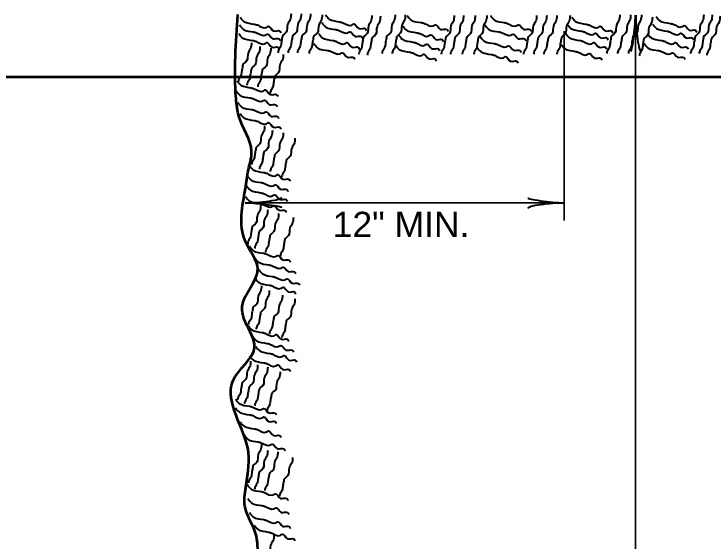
# Model space of a CAD drawing. Extents: x -488 to 193, y 19 to 459.
# Drawn here: x -190.5 to -135, y 277.1 to 318.9 of the extents above; entities that cross this region are included whole.
import ezdxf
from ezdxf.enums import TextEntityAlignment as Align

# ---------------------------------------------------------------- set-up
doc = ezdxf.new("R2010")
doc.units = 0
doc.header["$LTSCALE"] = 0.8
doc.layers.add('1', color=7, linetype='Continuous', lineweight=40)

msp = doc.modelspace()

# ---------------------------------------------------------------- linework, layer by layer
at = {"layer": '1', "lineweight": 35}
for p, q in [((-141.2341, 224.8116), (-141.2341, 318.7816)), ((-146.8977, 317.5241), (-146.8977, 302.5241)), ((-146.8977, 303.9148), (-172.1522, 303.9148))]:
    msp.add_line(p, q, dxfattribs=at)
at = {"layer": '1', "lineweight": 53}
msp.add_line((-271.5283, 313.9212), (-111.5283, 313.9212), dxfattribs=at)
at = {"layer": '1'}
for centre, major_axis, ratio, start_param, end_param in [((-141.4457, 317.6611), (-0.1757, -1.7565), 0.07063, 6.2823074, 8.5597026), ((-141.4457, 317.6611), (-0.1757, -1.7565), 0.07063, 6.2823074, 8.5597026), ((-140.9578, 317.6904), (-0.1562, 1.7857), 0.122415, 0.8963533, 3.1415927), ((-140.9578, 317.6904), (-0.1562, 1.7857), 0.122415, 0.8963533, 3.1415927), ((-171.0317, 303.7032), (1.7565, -0.1757), 0.07063, 6.2823074, 8.5597026), ((-171.0317, 303.7032), (1.7565, -0.1757), 0.07063, 6.2823074, 8.5597026), ((-171.0611, 304.1911), (-1.7857, -0.1562), 0.122415, 0.8963533, 3.1415927), ((-171.0611, 304.1911), (-1.7857, -0.1562), 0.122415, 0.8963533, 3.1415927), ((-147.9889, 303.6385), (1.7857, 0.1562), 0.122415, 0.8963533, 3.1415927), ((-148.0182, 304.1264), (1.7565, -0.1757), 0.07063, 3.1407148, 5.41811)]:
    msp.add_ellipse(centre, major_axis=major_axis, ratio=ratio, start_param=start_param, end_param=end_param, dxfattribs=at)
for points in [[(-168.5302, 318.8906), (-168.6157, 318.4057), (-168.801, 318.0633), (-168.9079, 317.457), (-169.2147, 317.1361), (-169.2359, 317.0149), (-169.3001, 316.6511), (-169.3642, 316.2873), (-169.5497, 315.9451), (-169.5711, 315.8237)], [(-167.7299, 318.8906), (-167.8154, 318.4057), (-168.0007, 318.0633), (-168.1077, 317.457), (-168.4144, 317.1361), (-168.4357, 317.0149), (-168.4998, 316.6511), (-168.5639, 316.2873), (-168.7494, 315.9451), (-168.7708, 315.8237)], [(-166.9913, 318.8906), (-167.0768, 318.4057), (-167.2621, 318.0633), (-167.369, 317.457), (-167.6757, 317.1361), (-167.697, 317.0149), (-167.7612, 316.6511), (-167.8252, 316.2873), (-168.0108, 315.9451), (-168.0322, 315.8237)], [(-172.5642, 318.6382), (-172.2713, 318.3047), (-171.4388, 318.0817), (-171.201, 318.018), (-170.4875, 317.8268), (-170.3367, 317.9138), (-169.9246, 317.5486), (-169.4172, 317.5399), (-169.3301, 317.3893)], [(-166.0678, 318.829), (-166.1533, 318.3441), (-166.3387, 318.0018), (-166.4456, 317.3954), (-166.7523, 317.0745), (-166.7736, 316.9533), (-166.8377, 316.5895), (-166.9018, 316.2258), (-167.0873, 315.8835), (-167.1087, 315.7622)], [(-165.7928, 318.8229), (-165.4999, 318.4893), (-164.6674, 318.2663), (-164.4296, 318.2027), (-163.7161, 318.0114), (-163.5652, 318.0985), (-163.1532, 317.7332), (-162.6457, 317.7246), (-162.5587, 317.5739)], [(-162.1281, 318.7674), (-162.2136, 318.2825), (-162.3989, 317.9402), (-162.5058, 317.3338), (-162.8126, 317.0129), (-162.8338, 316.8918), (-162.898, 316.5279), (-162.9621, 316.1642), (-163.1476, 315.8219), (-163.169, 315.7006)], [(-161.4509, 318.7059), (-161.5364, 318.221), (-161.7217, 317.8787), (-161.8287, 317.2723), (-162.1354, 316.9514), (-162.1567, 316.8302), (-162.2208, 316.4664), (-162.2849, 316.1027), (-162.4704, 315.7604), (-162.4918, 315.6391)], [(-160.2813, 318.829), (-160.3668, 318.3441), (-160.5522, 318.0018), (-160.6591, 317.3954), (-160.9658, 317.0745), (-160.9871, 316.9533), (-161.0512, 316.5895), (-161.1153, 316.2258), (-161.3008, 315.8835), (-161.3222, 315.7622)], [(-159.481, 318.829), (-159.5665, 318.3441), (-159.7518, 318.0018), (-159.8587, 317.3954), (-160.1655, 317.0745), (-160.1867, 316.9533), (-160.2509, 316.5895), (-160.315, 316.2258), (-160.5005, 315.8835), (-160.5219, 315.7622)], [(-159.3291, 318.7614), (-159.0362, 318.4278), (-158.2037, 318.2048), (-157.9658, 318.1412), (-157.2523, 317.9499), (-157.1015, 318.037), (-156.6894, 317.6717), (-156.182, 317.6631), (-156.0949, 317.5124)], [(-155.6028, 318.7674), (-155.6883, 318.2825), (-155.8737, 317.9402), (-155.9806, 317.3338), (-156.2873, 317.0129), (-156.3086, 316.8918), (-156.3727, 316.5279), (-156.4368, 316.1642), (-156.6223, 315.8219), (-156.6437, 315.7006)], [(-154.8642, 318.7674), (-154.9497, 318.2825), (-155.135, 317.9402), (-155.2419, 317.3338), (-155.5487, 317.0129), (-155.5699, 316.8918), (-155.6341, 316.5279), (-155.6982, 316.1642), (-155.8837, 315.8219), (-155.9051, 315.7006)], [(-153.9408, 318.7674), (-154.0263, 318.2825), (-154.2116, 317.9402), (-154.3185, 317.3338), (-154.6252, 317.0129), (-154.6465, 316.8918), (-154.7107, 316.5279), (-154.7747, 316.1642), (-154.9603, 315.8219), (-154.9817, 315.7006)], [(-153.0174, 318.7674), (-153.1029, 318.2825), (-153.2883, 317.9402), (-153.3952, 317.3338), (-153.7019, 317.0129), (-153.7232, 316.8918), (-153.7873, 316.5279), (-153.8514, 316.1642), (-154.0369, 315.8219), (-154.0583, 315.7006)], [(-152.7423, 318.7614), (-152.4494, 318.4278), (-151.6169, 318.2048), (-151.3791, 318.1412), (-150.6656, 317.9499), (-150.5147, 318.037), (-150.1027, 317.6717), (-149.5952, 317.6631), (-149.5082, 317.5124)], [(-149.0777, 318.7675), (-149.1632, 318.2826), (-149.3485, 317.9402), (-149.4554, 317.3339), (-149.7622, 317.013), (-149.7834, 316.8918), (-149.8476, 316.528), (-149.9117, 316.1642), (-150.0972, 315.822), (-150.1186, 315.7007)], [(-148.2774, 318.7675), (-148.3629, 318.2826), (-148.5482, 317.9402), (-148.6552, 317.3339), (-148.9619, 317.013), (-148.9832, 316.8918), (-149.0473, 316.528), (-149.1114, 316.1642), (-149.2969, 315.822), (-149.3183, 315.7007)], [(-147.4772, 318.7675), (-147.5627, 318.2826), (-147.748, 317.9402), (-147.8549, 317.3339), (-148.1617, 317.013), (-148.1829, 316.8918), (-148.2471, 316.528), (-148.3112, 316.1642), (-148.4967, 315.822), (-148.5181, 315.7007)], [(-146.4307, 318.7675), (-146.5162, 318.2826), (-146.7015, 317.9402), (-146.8084, 317.3339), (-147.1152, 317.013), (-147.1364, 316.8918), (-147.2006, 316.528), (-147.2647, 316.1642), (-147.4502, 315.822), (-147.4716, 315.7007)], [(-146.2788, 318.6383), (-145.9858, 318.3048), (-145.1533, 318.0817), (-144.9155, 318.0181), (-144.202, 317.8268), (-144.0512, 317.9139), (-143.6391, 317.5487), (-143.1317, 317.54), (-143.0446, 317.3893)], [(-142.4909, 318.829), (-142.5764, 318.3441), (-142.7618, 318.0018), (-142.8687, 317.3954), (-143.1754, 317.0745), (-143.1967, 316.9533), (-143.2608, 316.5895), (-143.3249, 316.2258), (-143.5104, 315.8835), (-143.5318, 315.7622)], [(-141.6291, 318.829), (-141.7146, 318.3441), (-141.8999, 318.0018), (-142.0068, 317.3954), (-142.3136, 317.0745), (-142.3348, 316.9533), (-142.399, 316.5895), (-142.4631, 316.2258), (-142.6486, 315.8835), (-142.67, 315.7622)], [(-140.7672, 318.829), (-140.8527, 318.3441), (-141.0381, 318.0018), (-141.145, 317.3954), (-141.4518, 317.0745), (-141.473, 316.9533), (-141.5372, 316.5895), (-141.6012, 316.2258), (-141.7867, 315.8835), (-141.8082, 315.7622)], [(-139.9054, 318.6443), (-139.9909, 318.1594), (-140.1762, 317.8171), (-140.2832, 317.2107), (-140.5899, 316.8898), (-140.6112, 316.7687), (-140.6753, 316.4048), (-140.7394, 316.0411), (-140.9249, 315.6988), (-140.9463, 315.5775)], [(-139.6304, 318.6997), (-139.3375, 318.3662), (-138.505, 318.1432), (-138.2672, 318.0795), (-137.5537, 317.8882), (-137.4028, 317.9753), (-136.9907, 317.6101), (-136.4833, 317.6014), (-136.3963, 317.4507)], [(-135.8426, 318.829), (-135.9281, 318.3441), (-136.1134, 318.0018), (-136.2203, 317.3954), (-136.5271, 317.0745), (-136.5483, 316.9533), (-136.6125, 316.5895), (-136.6766, 316.2258), (-136.8621, 315.8835), (-136.8835, 315.7622)], [(-135.1654, 318.829), (-135.2509, 318.3441), (-135.4363, 318.0018), (-135.5432, 317.3954), (-135.8499, 317.0745), (-135.8712, 316.9533), (-135.9353, 316.5895), (-135.9994, 316.2258), (-136.1849, 315.8835), (-136.2063, 315.7622)], [(-134.5498, 318.7058), (-134.6353, 318.2209), (-134.8207, 317.8786), (-134.9276, 317.2722), (-135.2343, 316.9513), (-135.2556, 316.8302), (-135.3197, 316.4663), (-135.3838, 316.1026), (-135.5693, 315.7603), (-135.5907, 315.639)], [(-172.6258, 318.0227), (-172.3329, 317.6891), (-171.5004, 317.4661), (-171.2626, 317.4024), (-170.5491, 317.2112), (-170.3982, 317.2982), (-169.9862, 316.933), (-169.4787, 316.9243), (-169.3917, 316.7737)], [(-166.1007, 318.2073), (-165.8077, 317.8737), (-164.9752, 317.6508), (-164.7374, 317.5871), (-164.0239, 317.3958), (-163.8731, 317.4829), (-163.461, 317.1177), (-162.9536, 317.109), (-162.8665, 316.9583)], [(-159.6985, 317.9612), (-159.4056, 317.6276), (-158.5731, 317.4046), (-158.3353, 317.3409), (-157.6217, 317.1497), (-157.4709, 317.2367), (-157.0588, 316.8715), (-156.5514, 316.8628), (-156.4643, 316.7122)], [(-153.1732, 318.0227), (-152.8803, 317.6891), (-152.0478, 317.4661), (-151.81, 317.4024), (-151.0965, 317.2112), (-150.9457, 317.2982), (-150.5336, 316.933), (-150.0262, 316.9243), (-149.9391, 316.7737)], [(-146.6481, 318.0842), (-146.3552, 317.7507), (-145.5227, 317.5277), (-145.2848, 317.464), (-144.5713, 317.2727), (-144.4205, 317.3598), (-144.0084, 316.9946), (-143.501, 316.9859), (-143.4139, 316.8352)], [(-139.8766, 318.0842), (-139.5837, 317.7506), (-138.7512, 317.5276), (-138.5133, 317.4639), (-137.7998, 317.2727), (-137.649, 317.3597), (-137.2369, 316.9945), (-136.7295, 316.9858), (-136.6424, 316.8352)], [(-172.6873, 317.3455), (-172.3944, 317.0119), (-171.5619, 316.7889), (-171.3241, 316.7253), (-170.6106, 316.534), (-170.4597, 316.6211), (-170.0477, 316.2558), (-169.5402, 316.2472), (-169.4532, 316.0965)], [(-166.3468, 317.3455), (-166.0539, 317.0119), (-165.2214, 316.7889), (-164.9836, 316.7253), (-164.2701, 316.534), (-164.1192, 316.6211), (-163.7072, 316.2558), (-163.1997, 316.2472), (-163.1127, 316.0965)], [(-160.0062, 317.2224), (-159.7133, 316.8888), (-158.8808, 316.6658), (-158.643, 316.6022), (-157.9295, 316.4109), (-157.7787, 316.498), (-157.3666, 316.1327), (-156.8592, 316.1241), (-156.7721, 315.9734)], [(-146.7712, 317.3456), (-146.4783, 317.012), (-145.6457, 316.789), (-145.4079, 316.7253), (-144.6944, 316.5341), (-144.5436, 316.6212), (-144.1315, 316.2559), (-143.6241, 316.2473), (-143.537, 316.0966)], [(-140.3075, 317.3455), (-140.0146, 317.0119), (-139.1821, 316.7889), (-138.9442, 316.7253), (-138.2308, 316.534), (-138.0799, 316.6211), (-137.6678, 316.2558), (-137.1604, 316.2472), (-137.0733, 316.0965)], [(-153.5426, 317.0993), (-153.2497, 316.7657), (-152.4172, 316.5428), (-152.1793, 316.4791), (-151.4658, 316.2878), (-151.315, 316.3749), (-150.9029, 316.0097), (-150.3955, 316.001), (-150.3084, 315.8503)], [(-171.6697, 316.6129), (-171.7552, 316.128), (-171.9405, 315.7857), (-172.0474, 315.1793), (-172.3542, 314.8584), (-172.3754, 314.7373), (-172.4396, 314.3734), (-172.5037, 314.0097), (-172.6892, 313.6674), (-172.7106, 313.5461)], [(-170.9926, 316.3051), (-171.0781, 315.8202), (-171.2634, 315.4778), (-171.3703, 314.8715), (-171.6771, 314.5506), (-171.6983, 314.4294), (-171.7625, 314.0656), (-171.8266, 313.7018), (-172.0121, 313.3596), (-172.0335, 313.2382)], [(-170.1308, 316.182), (-170.2163, 315.6971), (-170.4016, 315.3547), (-170.5085, 314.7484), (-170.8152, 314.4275), (-170.8365, 314.3063), (-170.9007, 313.9425), (-170.9647, 313.5788), (-171.1502, 313.2365), (-171.1717, 313.1152)], [(-166.7163, 316.5453), (-166.4233, 316.2117), (-165.5908, 315.9887), (-165.353, 315.925), (-164.6395, 315.7337), (-164.4887, 315.8208), (-164.0766, 315.4556), (-163.5692, 315.4469), (-163.4821, 315.2962)], [(-160.2525, 316.4222), (-159.9596, 316.0886), (-159.1271, 315.8656), (-158.8893, 315.8019), (-158.1757, 315.6107), (-158.0249, 315.6977), (-157.6128, 315.3325), (-157.1054, 315.3238), (-157.0183, 315.1732)], [(-153.7888, 316.2375), (-153.4959, 315.9039), (-152.6634, 315.6809), (-152.4256, 315.6173), (-151.7121, 315.426), (-151.5613, 315.5131), (-151.1492, 315.1478), (-150.6418, 315.1392), (-150.5547, 314.9885)], [(-147.1406, 316.4837), (-146.8477, 316.1502), (-146.0152, 315.9272), (-145.7773, 315.8635), (-145.0638, 315.6722), (-144.913, 315.7593), (-144.5009, 315.3941), (-143.9935, 315.3854), (-143.9064, 315.2347)], [(-140.5538, 316.5453), (-140.2608, 316.2117), (-139.4283, 315.9887), (-139.1905, 315.925), (-138.477, 315.7337), (-138.3262, 315.8208), (-137.9141, 315.4556), (-137.4067, 315.4469), (-137.3196, 315.2962)], [(-169.1458, 315.6895), (-169.2313, 315.2046), (-169.4167, 314.8623), (-169.5236, 314.2559), (-169.8303, 313.935), (-169.8516, 313.8138), (-169.9158, 313.45), (-169.9798, 313.0863), (-170.1653, 312.744), (-170.1867, 312.6227)], [(-172.8105, 313.5905), (-172.5176, 313.2569), (-171.6851, 313.0339), (-171.4472, 312.9702), (-170.7337, 312.779), (-170.5829, 312.8661), (-170.1708, 312.5008), (-169.6634, 312.4922), (-169.5763, 312.3415)], [(-172.872, 312.7903), (-172.5791, 312.4567), (-171.7466, 312.2337), (-171.5087, 312.17), (-170.7952, 311.9787), (-170.6444, 312.0658), (-170.2323, 311.7006), (-169.7249, 311.6919), (-169.6378, 311.5412)], [(-172.7489, 311.8668), (-172.456, 311.5333), (-171.6235, 311.3102), (-171.3857, 311.2466), (-170.6722, 311.0553), (-170.5213, 311.1424), (-170.1093, 310.7772), (-169.6018, 310.7685), (-169.5147, 310.6178)], [(-172.5642, 311.005), (-172.2713, 310.6714), (-171.4388, 310.4484), (-171.201, 310.3847), (-170.4875, 310.1935), (-170.3367, 310.2806), (-169.9246, 309.9153), (-169.4172, 309.9067), (-169.3301, 309.756)], [(-170.6232, 310.0261), (-170.7087, 309.5412), (-170.8941, 309.1988), (-171.001, 308.5925), (-171.3077, 308.2716), (-171.329, 308.1504), (-171.3932, 307.7866), (-171.4572, 307.4228), (-171.6428, 307.0806), (-171.6642, 306.9592)], [(-170.0076, 309.6567), (-170.0931, 309.1718), (-170.2784, 308.8295), (-170.3853, 308.2232), (-170.6921, 307.9022), (-170.7133, 307.7811), (-170.7775, 307.4172), (-170.8416, 307.0535), (-171.0271, 306.7113), (-171.0485, 306.5899)], [(-169.1458, 309.4721), (-169.2313, 308.9872), (-169.4167, 308.6448), (-169.5236, 308.0385), (-169.8303, 307.7176), (-169.8516, 307.5964), (-169.9158, 307.2326), (-169.9798, 306.8688), (-170.1653, 306.5266), (-170.1867, 306.4052)], [(-168.2224, 309.0412), (-168.3079, 308.5562), (-168.4932, 308.2139), (-168.6002, 307.6076), (-168.9069, 307.2867), (-168.9282, 307.1655), (-168.9923, 306.8017), (-169.0564, 306.4379), (-169.2419, 306.0957), (-169.2633, 305.9743)], [(-171.8256, 306.8806), (-171.5327, 306.547), (-170.7002, 306.324), (-170.4623, 306.2603), (-169.7488, 306.0691), (-169.598, 306.1562), (-169.1859, 305.7909), (-168.6785, 305.7822), (-168.5914, 305.6316)], [(-172.0102, 306.0802), (-171.7173, 305.7467), (-170.8848, 305.5237), (-170.647, 305.46), (-169.9335, 305.2688), (-169.7827, 305.3558), (-169.3706, 304.9906), (-168.8632, 304.9819), (-168.7761, 304.8313)], [(-172.0718, 305.28), (-171.7789, 304.9464), (-170.9464, 304.7234), (-170.7086, 304.6597), (-169.9951, 304.4685), (-169.8442, 304.5556), (-169.4322, 304.1903), (-168.9247, 304.1817), (-168.8377, 304.031)], [(-172.1333, 304.4182), (-171.8404, 304.0846), (-171.0079, 303.8616), (-170.7701, 303.7979), (-170.0566, 303.6067), (-169.9057, 303.6937), (-169.4937, 303.3285), (-168.9862, 303.3198), (-168.8992, 303.1692)], [(-170.931, 303.7472), (-171.0165, 303.2622), (-171.2018, 302.9199), (-171.3088, 302.3136), (-171.6155, 301.9927), (-171.6368, 301.8715), (-171.7009, 301.5077), (-171.765, 301.1439), (-171.9505, 300.8017), (-171.9719, 300.6803)], [(-170.377, 303.3778), (-170.4625, 302.8929), (-170.6478, 302.5506), (-170.7548, 301.9443), (-171.0615, 301.6233), (-171.0828, 301.5022), (-171.1469, 301.1383), (-171.211, 300.7746), (-171.3965, 300.4323), (-171.4179, 300.311)], [(-169.5152, 303.07), (-169.6007, 302.5851), (-169.786, 302.2428), (-169.8929, 301.6364), (-170.1997, 301.3155), (-170.2209, 301.1943), (-170.2851, 300.8305), (-170.3492, 300.4667), (-170.5347, 300.1245), (-170.5561, 300.0032)], [(-168.3455, 302.7622), (-168.431, 302.2773), (-168.6163, 301.935), (-168.7233, 301.3287), (-169.03, 301.0077), (-169.0512, 300.8866), (-169.1154, 300.5227), (-169.1795, 300.159), (-169.365, 299.8168), (-169.3864, 299.6954)], [(-171.8255, 300.4784), (-171.5326, 300.1448), (-170.7001, 299.9218), (-170.4622, 299.8582), (-169.7488, 299.6669), (-169.5979, 299.754), (-169.1858, 299.3888), (-168.6784, 299.3801), (-168.5913, 299.2294)], [(-171.3946, 299.5551), (-171.1017, 299.2215), (-170.2692, 298.9985), (-170.0313, 298.9348), (-169.3178, 298.7436), (-169.167, 298.8307), (-168.7549, 298.4654), (-168.2475, 298.4567), (-168.1604, 298.3061)], [(-171.0868, 298.6317), (-170.7939, 298.2981), (-169.9614, 298.0751), (-169.7236, 298.0114), (-169.0101, 297.8202), (-168.8593, 297.9072), (-168.4472, 297.542), (-167.9398, 297.5333), (-167.8527, 297.3827)], [(-171.3946, 297.9545), (-171.1017, 297.6209), (-170.2692, 297.3979), (-170.0313, 297.3342), (-169.3178, 297.143), (-169.167, 297.2301), (-168.7549, 296.8648), (-168.2475, 296.8562), (-168.1604, 296.7055)], [(-170.8694, 297.345), (-170.9549, 296.8601), (-171.1402, 296.5177), (-171.2472, 295.9114), (-171.5539, 295.5905), (-171.5752, 295.4693), (-171.6393, 295.1055), (-171.7034, 294.7417), (-171.8889, 294.3995), (-171.9103, 294.2782)], [(-170.2538, 296.9757), (-170.3393, 296.4907), (-170.5247, 296.1484), (-170.6316, 295.5421), (-170.9383, 295.2212), (-170.9596, 295.1), (-171.0238, 294.7362), (-171.0878, 294.3724), (-171.2733, 294.0302), (-171.2947, 293.9088)], [(-169.2073, 296.6063), (-169.2928, 296.1214), (-169.4782, 295.7791), (-169.5851, 295.1728), (-169.8918, 294.8518), (-169.9131, 294.7307), (-169.9772, 294.3668), (-170.0413, 294.0031), (-170.2268, 293.6608), (-170.2482, 293.5395)], [(-168.2224, 296.2985), (-168.3079, 295.8136), (-168.4932, 295.4712), (-168.6002, 294.8649), (-168.9069, 294.544), (-168.9282, 294.4228), (-168.9923, 294.059), (-169.0564, 293.6952), (-169.2419, 293.353), (-169.2633, 293.2317)], [(-171.9487, 294.1995), (-171.6557, 293.8659), (-170.8233, 293.6429), (-170.5854, 293.5793), (-169.8719, 293.388), (-169.7211, 293.4751), (-169.309, 293.1098), (-168.8016, 293.1012), (-168.7145, 292.9505)], [(-171.5793, 293.3377), (-171.2863, 293.0041), (-170.4538, 292.7811), (-170.216, 292.7174), (-169.5025, 292.5262), (-169.3517, 292.6132), (-168.9396, 292.248), (-168.4322, 292.2393), (-168.3451, 292.0887)], [(-171.3331, 292.5374), (-171.0402, 292.2038), (-170.2077, 291.9808), (-169.9698, 291.9172), (-169.2563, 291.7259), (-169.1055, 291.813), (-168.6934, 291.4477), (-168.186, 291.4391), (-168.0989, 291.2884)], [(-171.8255, 291.7987), (-171.5326, 291.4652), (-170.7001, 291.2422), (-170.4622, 291.1785), (-169.7488, 290.9873), (-169.5979, 291.0743), (-169.1858, 290.7091), (-168.6784, 290.7004), (-168.5913, 290.5498)], [(-171.7312, 291.3738), (-171.8167, 290.8889), (-172.0021, 290.5466), (-172.109, 289.9402), (-172.4158, 289.6193), (-172.437, 289.4982), (-172.5012, 289.1343), (-172.5652, 288.7706), (-172.7507, 288.4283), (-172.7722, 288.307)], [(-171.1772, 291.066), (-171.2627, 290.5811), (-171.448, 290.2387), (-171.5549, 289.6324), (-171.8617, 289.3115), (-171.8829, 289.1903), (-171.9471, 288.8265), (-172.0112, 288.4627), (-172.1967, 288.1205), (-172.2181, 287.9992)], [(-170.3769, 290.8813), (-170.4624, 290.3964), (-170.6478, 290.0541), (-170.7547, 289.4477), (-171.0614, 289.1268), (-171.0827, 289.0057), (-171.1468, 288.6418), (-171.2109, 288.2781), (-171.3964, 287.9358), (-171.4178, 287.8145)], [(-169.392, 290.512), (-169.4775, 290.0271), (-169.6628, 289.6848), (-169.7697, 289.0784), (-170.0765, 288.7575), (-170.0977, 288.6363), (-170.1619, 288.2725), (-170.226, 287.9087), (-170.4115, 287.5665), (-170.4329, 287.4452)], [(-172.9336, 288.3514), (-172.6407, 288.0178), (-171.8082, 287.7948), (-171.5703, 287.7312), (-170.8568, 287.5399), (-170.706, 287.627), (-170.2939, 287.2618), (-169.7865, 287.2531), (-169.6994, 287.1024)], [(-172.9336, 287.6743), (-172.6407, 287.3408), (-171.8082, 287.1178), (-171.5703, 287.0541), (-170.8568, 286.8628), (-170.706, 286.9499), (-170.2939, 286.5847), (-169.7865, 286.576), (-169.6994, 286.4253)], [(-172.5642, 286.5662), (-172.2713, 286.2327), (-171.4388, 286.0097), (-171.201, 285.946), (-170.4875, 285.7548), (-170.3367, 285.8418), (-169.9246, 285.4766), (-169.4172, 285.4679), (-169.3301, 285.3173)], [(-172.2565, 285.5197), (-171.9636, 285.1862), (-171.1311, 284.9632), (-170.8932, 284.8995), (-170.1797, 284.7082), (-170.0289, 284.7953), (-169.6168, 284.4301), (-169.1094, 284.4214), (-169.0223, 284.2707)], [(-170.8693, 284.787), (-170.9548, 284.3021), (-171.1402, 283.9597), (-171.2471, 283.3534), (-171.5538, 283.0325), (-171.5751, 282.9113), (-171.6393, 282.5475), (-171.7033, 282.1837), (-171.8888, 281.8415), (-171.9102, 281.7202)], [(-170.3769, 284.2946), (-170.4624, 283.8097), (-170.6478, 283.4673), (-170.7547, 282.861), (-171.0614, 282.5401), (-171.0827, 282.4189), (-171.1468, 282.0551), (-171.2109, 281.6913), (-171.3964, 281.3491), (-171.4178, 281.2278)], [(-169.5767, 284.1714), (-169.6622, 283.6865), (-169.8475, 283.3442), (-169.9544, 282.7378), (-170.2612, 282.4169), (-170.2824, 282.2957), (-170.3466, 281.9319), (-170.4107, 281.5682), (-170.5962, 281.2259), (-170.6176, 281.1046)], [(-168.407, 283.7405), (-168.4925, 283.2556), (-168.6778, 282.9133), (-168.7848, 282.3069), (-169.0915, 281.986), (-169.1128, 281.8648), (-169.1769, 281.501), (-169.241, 281.1372), (-169.4265, 280.795), (-169.4479, 280.6737)], [(-172.0102, 281.58), (-171.7173, 281.2464), (-170.8848, 281.0234), (-170.647, 280.9597), (-169.9335, 280.7685), (-169.7827, 280.8556), (-169.3706, 280.4903), (-168.8632, 280.4817), (-168.7761, 280.331)], [(-171.9487, 280.4719), (-171.6557, 280.1383), (-170.8233, 279.9153), (-170.5854, 279.8517), (-169.8719, 279.6604), (-169.7211, 279.7475), (-169.309, 279.3822), (-168.8016, 279.3736), (-168.7145, 279.2229)], [(-171.8255, 279.3638), (-171.5326, 279.0302), (-170.7001, 278.8073), (-170.4622, 278.7436), (-169.7488, 278.5523), (-169.5979, 278.6394), (-169.1858, 278.2742), (-168.6784, 278.2655), (-168.5913, 278.1148)], [(-171.4562, 278.3789), (-171.1633, 278.0453), (-170.3307, 277.8223), (-170.0929, 277.7587), (-169.3794, 277.5674), (-169.2286, 277.6545), (-168.8165, 277.2892), (-168.3091, 277.2806), (-168.222, 277.1299)], [(-169.8844, 277.5847), (-169.9699, 277.0997), (-170.1552, 276.7574), (-170.2622, 276.1511), (-170.5689, 275.8302), (-170.5902, 275.709), (-170.6543, 275.3452), (-170.7184, 274.9814), (-170.9039, 274.6392), (-170.9253, 274.5178)]]:
    msp.add_spline(points, degree=3, dxfattribs=at)
at = {"layer": '1', "lineweight": 53}
msp.add_spline([(-212.7425, 318.8428), (-213.2734, 312.6869), (-212.2884, 310.2246), (-213.2734, 308.0085), (-212.5347, 306.0386), (-213.2734, 303.3301), (-212.2884, 301.6064), (-212.0422, 299.3903), (-212.2884, 295.943), (-212.5347, 294.2194), (-213.5196, 292.9882), (-213.7658, 292.2495), (-213.2734, 291.0183), (-213.0272, 289.5409), (-212.7809, 287.8173), (-212.5347, 286.0937), (-212.5347, 284.1237), (-211.5497, 281.4152), (-211.796, 279.6916), (-212.2884, 278.7066), (-212.2884, 275.9981), (-212.0422, 272.797), (-212.2884, 271.5658), (-212.2884, 268.8572), (-212.7809, 265.41), (-212.7809, 262.9477), (-213.7658, 259.7466), (-213.0272, 258.0229), (-213.2734, 255.8068), (-213.5196, 253.0982), (-213.2734, 251.3746), (-213.0272, 248.4198), (-212.7809, 246.6962), (-213.0272, 244.7263), (-213.0272, 241.5252), (-212.2884, 240.7866), (-212.7809, 236.8468), (-212.7809, 234.6307), (-212.5347, 233.1532), (-213.0272, 230.1985), (-212.5347, 228.9673), (-213.0272, 226.7512), (-212.5347, 225.7662), (-210.5648, 223.7964), (-208.8412, 224.2888), (-207.1175, 225.52), (-205.6401, 224.2888), (-204.1627, 224.0426), (-200.9617, 224.0426), (-197.7606, 225.2738), (-196.7757, 224.5351), (-192.5897, 224.5351), (-188.8962, 225.0276), (-186.9263, 224.5351), (-182.7403, 225.0276), (-181.2629, 224.7813), (-176.8307, 225.0276), (-176.3382, 224.2888), (-173.3834, 224.7813), (-171.1673, 227.7362), (-171.4136, 229.4597), (-171.6598, 230.4447), (-173.1372, 235.1232), (-171.1673, 238.3242), (-172.3985, 241.0327), (-172.3985, 242.0177), (-171.4136, 243.7413), (-171.906, 246.4499), (-171.1673, 247.6811), (-170.1824, 250.1434), (-171.6598, 254.3294), (-171.6598, 255.8068), (-171.4136, 257.5305), (-172.1522, 259.7466), (-171.906, 261.224), (-172.1522, 263.9326), (-173.1372, 267.3798), (-171.6598, 270.0884), (-171.4136, 272.3045), (-171.1673, 275.9981), (-171.4136, 277.9679), (-172.1522, 279.6916), (-172.1522, 281.169), (-171.906, 284.1237), (-172.891, 287.0786), (-173.1372, 289.7872), (-171.4136, 292.4957), (-172.1522, 294.4656), (-172.3985, 295.6968), (-171.1673, 298.6516), (-172.1522, 300.8677), (-172.1522, 305.0537), (-171.906, 306.5311), (-171.6598, 308.0085), (-172.6447, 310.7171), (-172.891, 312.1945), (-172.7425, 318.8428)], degree=3, dxfattribs=at)

# ---------------------------------------------------------------- texts
at = {"layer": '1', "width": 1.05}
msp.add_text('12" MIN.', height=2, dxfattribs=at).set_placement((-159.816, 301.2099), align=Align.CENTER)

doc.saveas('drawing.dxf')
